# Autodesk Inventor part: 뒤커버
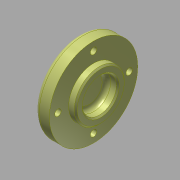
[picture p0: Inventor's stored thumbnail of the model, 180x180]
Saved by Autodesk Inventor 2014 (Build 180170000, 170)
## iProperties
Created: 2015-12
Part Number: 뒤커버
Document SubType Name: Modeling
Designer: mdu
Density: 2.71 g/cm^3
Material: 알루미늄 6061
Mass: 80.8084 g
Surface Area: 93.0378 cm^2
Volume: 29.8186 cm^3
Appearance: 알루미늄 - 평지
Author: mdu
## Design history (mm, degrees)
sketch "스케치1"
  geometry: L1 (-7.5, 0)-(7.5, 0); L2 (-7.5, 0)-(-7.5, 31); L3 (-7.5, 31)-(2.5, 31); L4 (2.5, 31)-(2.5, 17.5); L5 (2.5, 17.5)-(7.5, 17.5); L6 (7.5, 17.5)-(7.5, 0); 2 further points
  constraints: 12 end point, 3 parallel, 1 coincident, 1 horizontal, 1 midpoint, 1 perpendicular
  dimensions: "d0" = 15 distance of L1.start L1.end; "d1" = 62 diameter of L3 L1; "d2" = 35 diameter of L5 L1; "d34" = 10 distance of L2.end L3.end
revolve "회전1" sketch "스케치1" stored, may be unused: angle "d6" = 90 deg
sketch "스케치2" dims "d32" = 50
  geometry: 3 further points
  constraints: 2 vertical alignment, 1 coincident, 2 other
hole "구멍1" sketch "스케치2" at (0, 25) diameter "d8" = 4.5; stored, may be unused: countersink angle "d12" = 90 deg, drill point angle "d14" = 118 deg; dims "d9" = 6, "d10" = 8, "d11" = 4.4, "d13" = 8
hole "구멍2" diameter "d20" = 24; stored, may be unused: countersink angle "d24" = 90 deg, drill point angle "d26" = 0 deg; dims "d18" = 10, "d19" = 10, "d21" = 6, "d22" = 8, "d23" = 4.4, "d25" = 8
fillet "모깎기1" dims "d27" = 3
fillet "모깎기2" dims "d28" = 3
chamfer "모따기1" distance "d29" = 1; stored, may be unused: second distance "d30" = 2, angle "d31" = 45 deg
node "솔리드1"
pattern_circular "원형 패턴1" dims angle "d16" = 360 deg
